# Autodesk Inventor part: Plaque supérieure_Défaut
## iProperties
Shininess: 64.0
Length Units: 11269
Angle Units: 11279
Time Units: 11290
Mass Units: 11283
Length Display Precision: 3
Angle Display Precision: 2
Compacted: True
Part Number: Plaque supérieure_Défaut
Document SubType Name: Modeling
Created: 2006-11
Material: Par défaut
Designer: profs_sti
Density: 0.0
Volumn: 0.0
Area: 0.0
PropertySet Name: Model Information
Control State: 0
Master: False
Checked Out: False
Author: profs_sti
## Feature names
1. Base1
